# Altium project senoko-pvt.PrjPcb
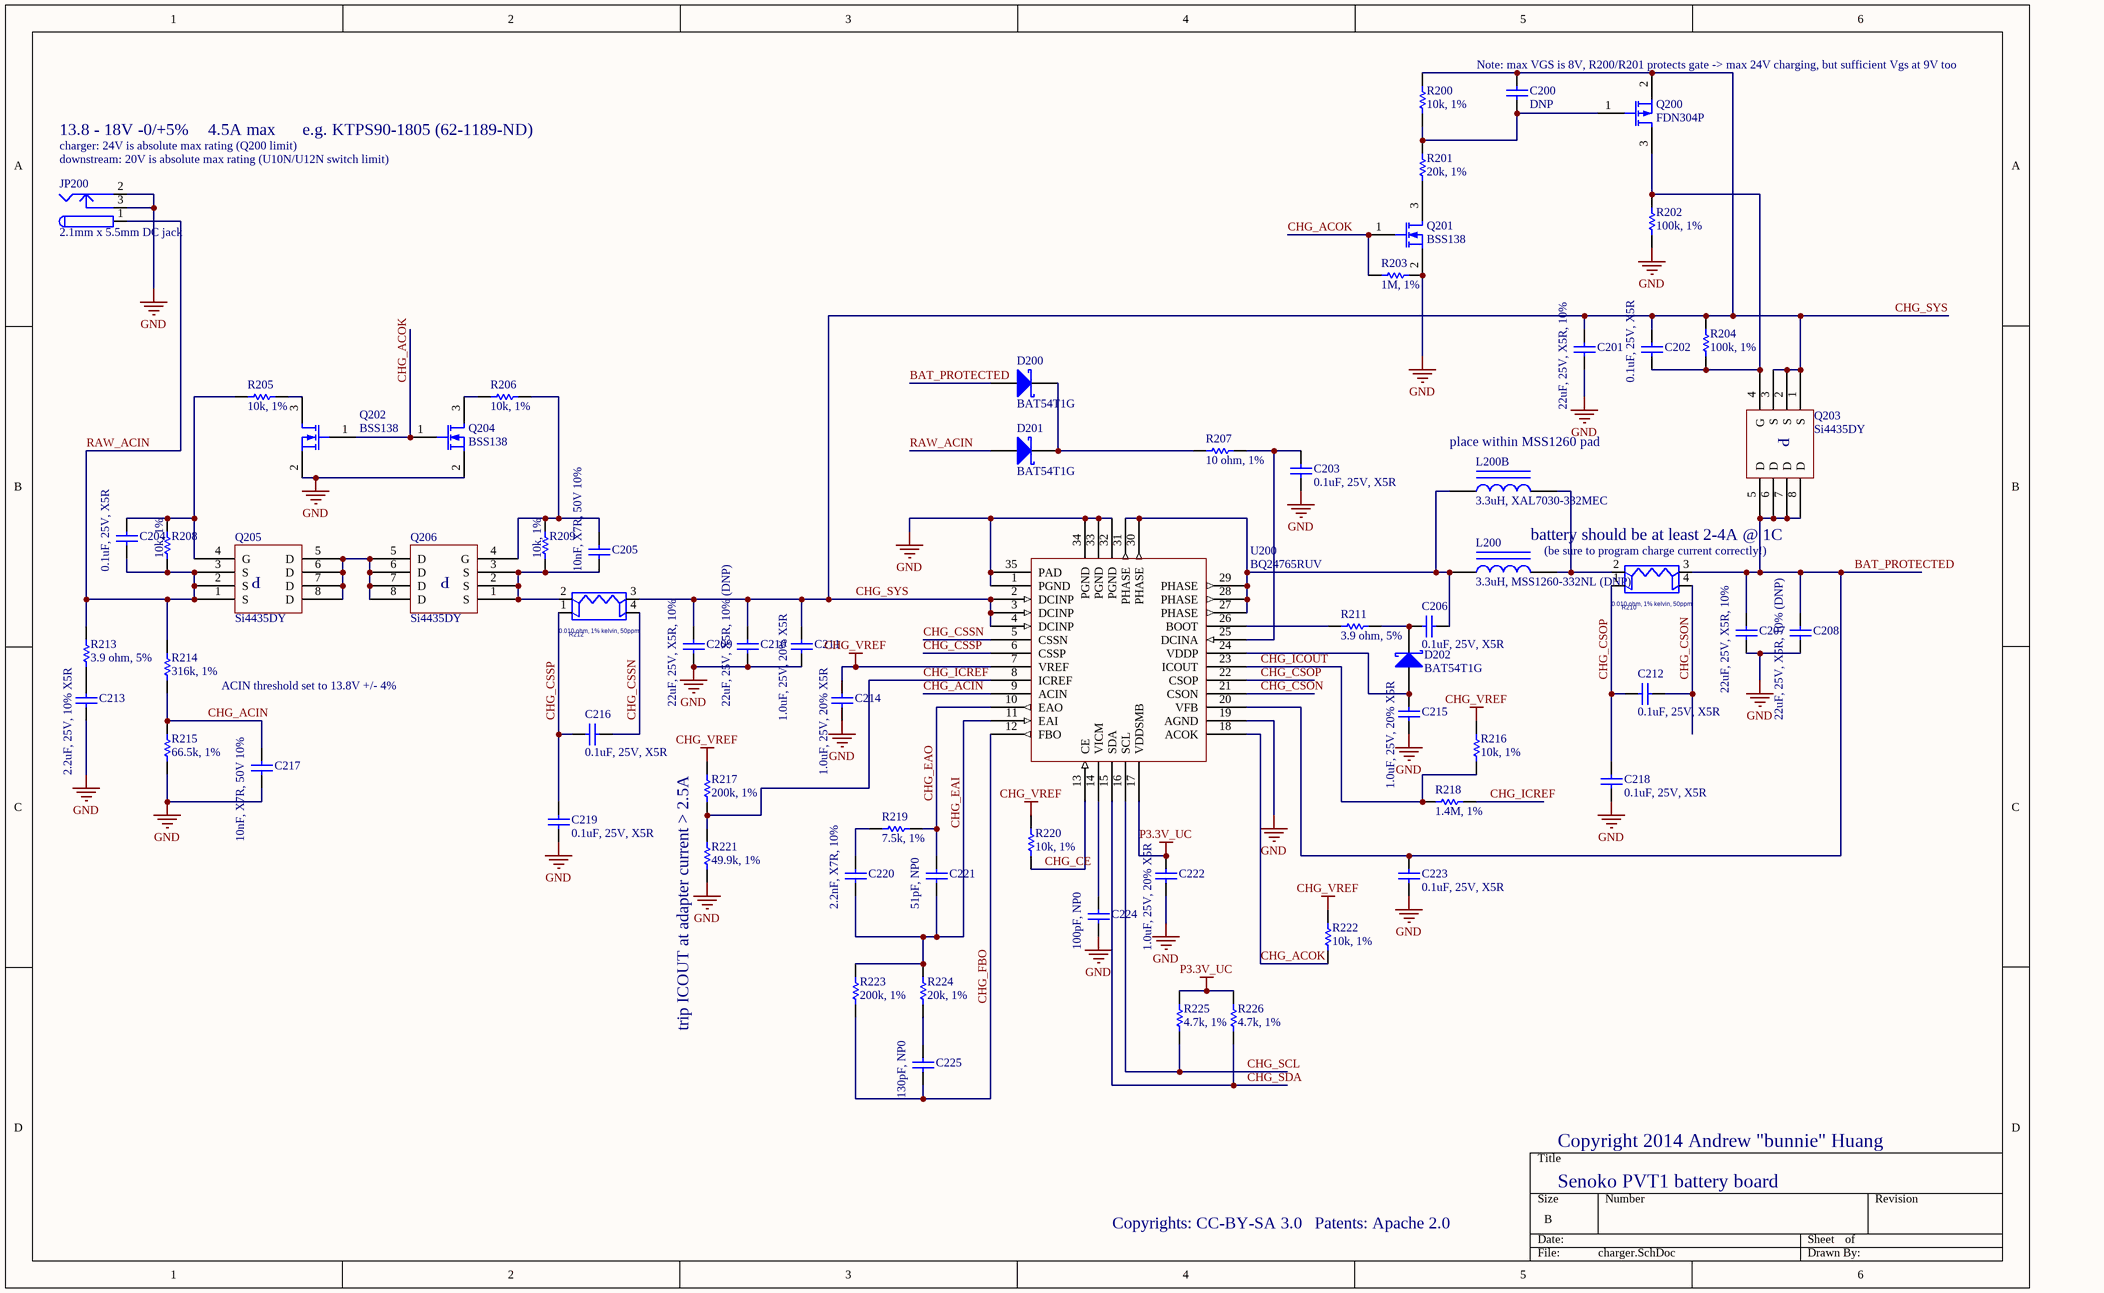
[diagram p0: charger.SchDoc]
3 sheets, 227 parts. Net scope: global (net labels, ports and power ports of the same name join across sheets).
Board file: senoko_pvt1.PcbDoc
Sheets:
  charger.SchDoc
  battery.SchDoc
  controller.SchDoc

## Sheet charger.SchDoc
size B; SheetNumber: 1

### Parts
C200  DNP  [CAPC1005N]
C201  22uF, 25V, X5R, 10%  [CAPC3225N]
C202  0.1uF, 25V, X5R  [CAPC1005N]
C203  0.1uF, 25V, X5R  [CAPC1005N]
C204  0.1uF, 25V, X5R  [CAPC1005N]
C205  10nF, X7R, 50V 10%  [CAPC1005N]
C206  0.1uF, 25V, X5R  [CAPC1005N]
C207  22uF, 25V, X5R, 10%  [CAPC3225N]
C208  22uF, 25V, X5R, 10% (DNP)  [CAPC3225N]
C209  22uF, 25V, X5R, 10%  [CAPC3225N]
C210  22uF, 25V, X5R, 10% (DNP)  [CAPC3225N]
C211  1.0uF, 25V, 20% X5R  [CAPC1608N]
C212  0.1uF, 25V, X5R  [CAPC1005N]
C213  2.2uF, 25V, 10% X5R  [CAPC1608N]
C214  1.0uF, 25V, 20% X5R  [CAPC1608N]
C215  1.0uF, 25V, 20% X5R  [CAPC1608N]
C216  0.1uF, 25V, X5R  [CAPC1005N]
C217  10nF, X7R, 50V 10%  [CAPC1005N]
C218  0.1uF, 25V, X5R  [CAPC1005N]
C219  0.1uF, 25V, X5R  [CAPC1005N]
C220  2.2nF, X7R, 10%  [CAPC1005N]
C221  51pF, NP0  [CAPC1005N]
C222  1.0uF, 25V, 20% X5R  [CAPC1608N]
C223  0.1uF, 25V, X5R  [CAPC1005N]
C224  100pF, NP0  [CAPC1005N]
C225  130pF, NP0  [CAPC1005N]
D200  BAT54T1G  [SOD123]
D201  BAT54T1G  [SOD123]
D202  BAT54T1G  [SOD123]
JP200  2.1mm x 5.5mm DC jack  [CUI_PJ_002AH_SMT]
L200  3.3uH, MSS1260-332NL (DNP)  [COILCRAFT_MSS1048]
L200B  3.3uH, XAL7030-332MEC  [COILCRAFT_XAL7030]
Q200  FDN304P  [SOT23-3N]
Q201  BSS138  [SOT23-3N]
Q202  BSS138  [SOT23-3N]
Q203  Si4435DY  [SOIC127P600-8AN]
Q204  BSS138  [SOT23-3N]
Q205  Si4435DY  [SOIC127P600-8AN]
Q206  Si4435DY  [SOIC127P600-8AN]
R200  10k, 1%  [RESC1005N]
R201  20k, 1%  [RESC1005N]
R202  100k, 1%  [RESC1005N]
R203  1M, 1%  [RESC1005N]
R204  100k, 1%  [RESC1005N]
R205  10k, 1%  [RESC1005N]
R206  10k, 1%  [RESC1005N]
R207  10 ohm, 1%  [RESC1005N]
R208  10k, 1%  [RESC1005N]
R209  10k, 1%  [RESC1005N]
R210  0.010 ohm, 1% kelvin, 50ppm  [OHMITE_LVK_1206_KELVIN]
R211  3.9 ohm, 5%  [RESC1005N]
R212  0.010 ohm, 1% kelvin, 50ppm  [OHMITE_LVK_1206_KELVIN]
R213  3.9 ohm, 5%  [RESC1005N]
R214  316k, 1%  [RESC1005N]
R215  66.5k, 1%  [RESC1005N]
R216  10k, 1%  [RESC1005N]
R217  200k, 1%  [RESC1005N]
R218  1.4M, 1%  [RESC1005N]
R219  7.5k, 1%  [RESC1005N]
R220  10k, 1%  [RESC1005N]
R221  49.9k, 1%  [RESC1005N]
R222  10k, 1%  [RESC1005N]
R223  200k, 1%  [RESC1005N]
R224  20k, 1%  [RESC1005N]
R225  4.7k, 1%  [RESC1005N]
R226  4.7k, 1%  [RESC1005N]
U200  BQ24765RUV  [TI_R-PVQFN-N34]

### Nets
CHG_VREF: C214.1 R216.1 R217.1 R220.1 R222.1 U200.7(VREF)
GND: C201.2 C203.2 C207.2 C208.2 C209.2 C210.2 C211.2 C213.2 C214.2 C215.2 C217.2 C218.1 C219.2 C222.2 C223.1 C224.2 JP200.2 JP200.3 Q201.2(S) Q202.2(S) Q204.2(S) R202.2 R203.1 R215.2 R221.2 U200.1(PGND) U200.19(AGND) U200.32(PGND) U200.33(PGND) U200.34(PGND) U200.35(PAD)
P3.3V_UC: C222.1 R225.1 R226.1 U200.17(VDDSMB)
BAT_PROTECTED: C207.1 C208.1 C223.2 D200.1(A) Q203.5(D) Q203.6(D) Q203.7(D) Q203.8(D) R210.3 U200.20(VFB)
CHG_ACIN: C217.1 R214.2 R215.1 U200.9(ACIN)
CHG_ACOK: Q201.1(G) Q202.1(G) Q204.1(G) R203.2 R222.2 U200.18(ACOK)
CHG_CE: R220.2 U200.13(CE)
CHG_CSON: C212.1 R210.4 U200.21(CSON)
CHG_CSOP: C212.2 C218.2 R210.1 U200.22(CSOP)
CHG_CSSN: C216.2 R212.4 U200.5(CSSN)
CHG_CSSP: C216.1 C219.1 R212.1 U200.6(CSSP)
CHG_EAI: C220.2 C221.2 R223.1 R224.1 U200.11(EAI)
CHG_EAO: C221.1 R219.2 U200.10(EAO)
CHG_FBO: C225.2 R223.2 U200.12(FBO)
CHG_ICOUT: R216.2 R218.2 U200.23(ICOUT)
CHG_ICREF: R217.2 R218.1 R221.1 U200.8(ICREF)
CHG_SCL: R225.2 U200.16(SCL)
CHG_SDA: R226.2 U200.15(SDA)
CHG_SYS: C200.2 C201.1 C202.1 C209.1 C210.1 C211.1 Q200.2(S) Q203.1(S) Q203.2(S) Q203.3(S) R200.1 R204.1 R212.3 U200.2(DCINP) U200.3(DCINP) U200.4(DCINP)
RAW_ACIN: C204.2 D201.1(A) JP200.1 Q205.1(S) Q205.2(S) Q205.3(S) R208.1 R213.1 R214.1
NetC200_1: C200.1 Q200.1(G) R200.2 R201.1
NetC202_2: C202.2 Q200.3(D) Q203.4(G) R202.1 R204.2
NetC203_1: C203.1 R207.2 U200.25(DCINA)
NetC204_1: C204.1 Q205.4(G) R205.1 R208.2
NetC205_1: C205.1 Q206.4(G) R206.2 R209.2
NetC205_2: C205.2 Q206.1(S) Q206.2(S) Q206.3(S) R209.1 R212.2
NetC206_1: C206.1 D202.2(K) R211.2
NetC206_2: C206.2 L200.1 L200B.1 U200.27(PHASE) U200.28(PHASE) U200.29(PHASE) U200.30(PHASE) U200.31(PHASE)
NetC213_1: C213.1 R213.2
NetC215_1: C215.1 D202.1(A) U200.24(VDDP)
NetC220_1: C220.1 R219.1
NetC224_1: C224.1 U200.14(VICM)
NetC225_1: C225.1 R224.2
NetD200_2: D200.2(K) D201.2(K) R207.1
NetL200_2: L200.2 L200B.2 R210.2
NetQ201_3: Q201.3(D) R201.2
NetQ202_3: Q202.3(D) R205.2
NetQ204_3: Q204.3(D) R206.1
NetQ205_5: Q205.5(D) Q205.6(D) Q205.7(D) Q205.8(D) Q206.5(D) Q206.6(D) Q206.7(D) Q206.8(D)
NetR211_1: R211.1 U200.26(BOOT)

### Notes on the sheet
- (near C200) Note: max VGS is 8V, R200/R201 protects gate -> max 24V charging, but sufficient Vgs at 9V too
- 13.8 - 18V -0/+5%
- (near JP200) charger: 24V is absolute max rating (Q200 limit)
- (near JP200) downstream: 20V is absolute max rating (U10N/U12N switch limit)
- 4.5A max
- e.g. KTPS90-1805 (62-1189-ND)
- (near L200B) place within MSS1260 pad
- battery should be at least 2-4A @ 1C
- (be sure to program charge current correctly!)
- ACIN threshold set to 13.8V +/- 4%
- trip ICOUT at adapter current > 2.5A
- Copyright 2014 Andrew "bunnie" Huang
- Copyrights: CC-BY-SA 3.0
- Patents: Apache 2.0
- Senoko PVT1 battery board

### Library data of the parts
C200-C225 = Cap Semi: Capacitor (Semiconductor SIM Model)
D200-D202 = D Schottky: Schottky Diode; Code - JEDEC: DO-214-AA
JP200 = PWR2.5: Low Voltage Power Supply Connector
L200 L200B = Inductor Iron: Magnetic-Core Inductor
Q200 = MOSFET-P: P-Channel MOSFET
Q201 Q202 Q204 = MOSFET-N: N-Channel MOSFET
Q203 Q205 Q206 = Si4435DY: Singre P-channel FET, 8A, 30V
R200 R201 R203 R205-R209 R211 R213-R226 = Res1: Resistor; Value: 100k
R202 R204 = Res1: Resistor
R210 R212 = RES_4TERM: PART_NUMBER: R00034-001; CDS_LMAN_SYM_OUTLINE: -100,25,100,-75; NEEDS_NO_SIZE: TRUE; PATH: I224; PN: #; OriginalSymbolOrigin: (-100,50); LOCATION: RN32; SEC: 1; XY: (-5650,2000); WATTAGE: 1/2W; PHYS_PAGE: 12; PACK_TYPE: RES1206_4T; MFG_PN: LVK12R020FER; MFG: OHMITE; DRAWING: @BROWNSTONE_LIB.BROWNSTONE(SCH_1):PAGE12; CDS_LIB: resistors
U200 = BQ24765RUV: SMBus-controlled battery charger with integrated FETs

## Sheet battery.SchDoc
size B; SheetNumber: 2
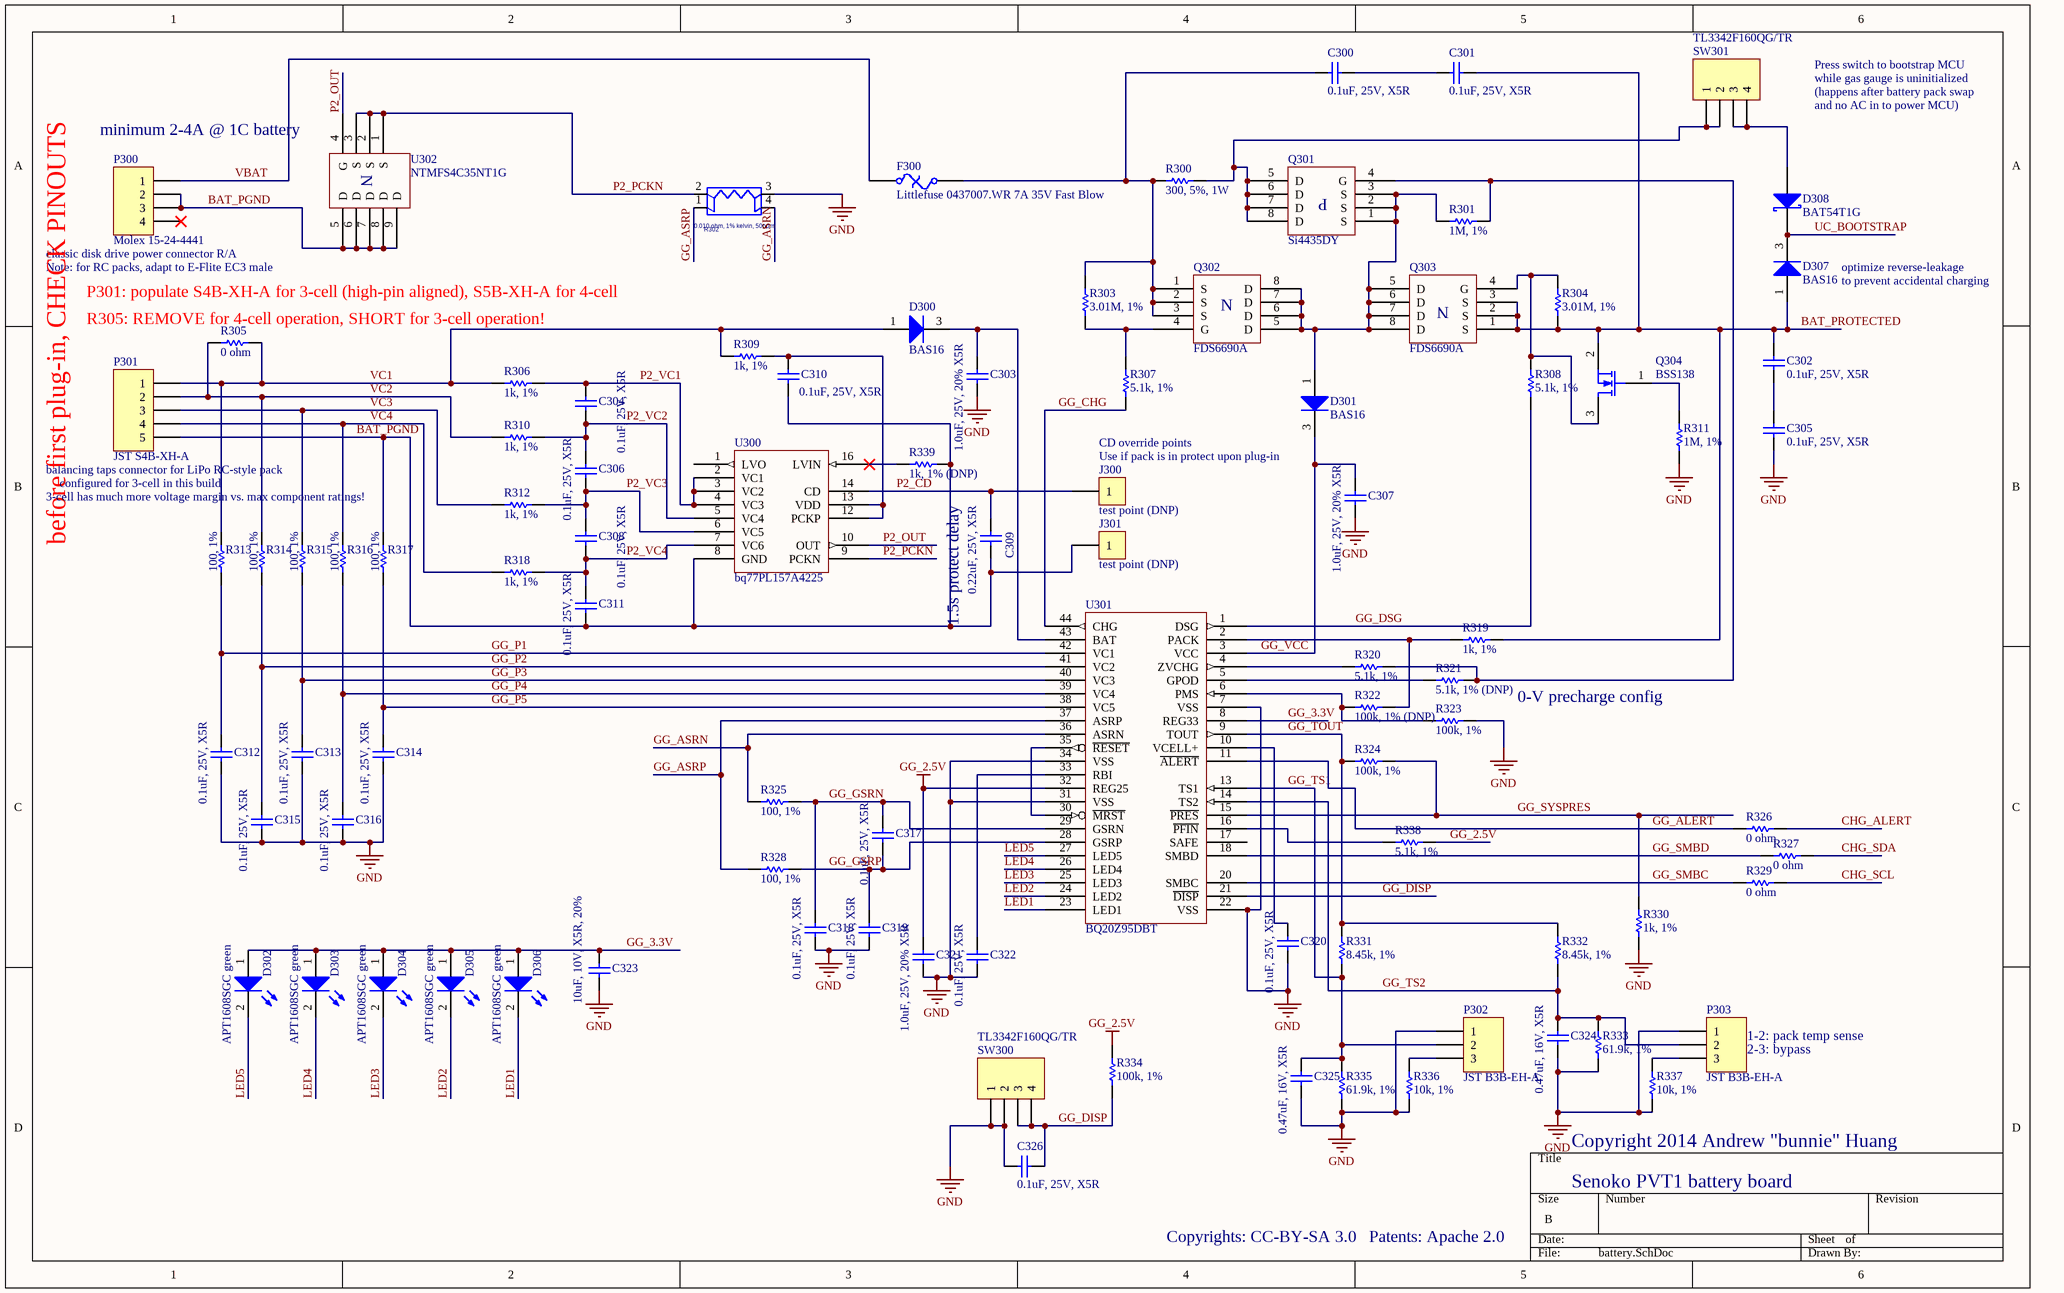
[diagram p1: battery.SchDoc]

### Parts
C300  0.1uF, 25V, X5R  [CAPC1005N]
C301  0.1uF, 25V, X5R  [CAPC1005N]
C302  0.1uF, 25V, X5R  [CAPC1005N]
C303  1.0uF, 25V, 20% X5R  [CAPC1608N]
C304  0.1uF, 25V, X5R  [CAPC1005N]
C305  0.1uF, 25V, X5R  [CAPC1005N]
C306  0.1uF, 25V, X5R  [CAPC1005N]
C307  1.0uF, 25V, 20% X5R  [CAPC1608N]
C308  0.1uF, 25V, X5R  [CAPC1005N]
C309  0.22uF, 25V, X5R  [CAPC1005N]
C310  0.1uF, 25V, X5R  [CAPC1005N]
C311  0.1uF, 25V, X5R  [CAPC1005N]
C312  0.1uF, 25V, X5R  [CAPC1005N]
C313  0.1uF, 25V, X5R  [CAPC1005N]
C314  0.1uF, 25V, X5R  [CAPC1005N]
C315  0.1uF, 25V, X5R  [CAPC1005N]
C316  0.1uF, 25V, X5R  [CAPC1005N]
C317  0.1uF, 25V, X5R  [CAPC1005N]
C318  0.1uF, 25V, X5R  [CAPC1005N]
C319  0.1uF, 25V, X5R  [CAPC1005N]
C320  0.1uF, 25V, X5R  [CAPC1005N]
C321  1.0uF, 25V, 20% X5R  [CAPC1608N]
C322  0.1uF, 25V, X5R  [CAPC1005N]
C323  10uF, 10V, X5R, 20%  [CAPC1608N]
C324  0.47uF, 16V, X5R  [CAPC1005N]
C325  0.47uF, 16V, X5R  [CAPC1005N]
C326  0.1uF, 25V, X5R  [CAPC1005N]
D300  BAS16  [SOT23-3N]
D301  BAS16  [SOT23-3N]
D302  APT1608SGC green  [CD1608-0603]
D303  APT1608SGC green  [CD1608-0603]
D304  APT1608SGC green  [CD1608-0603]
D305  APT1608SGC green  [CD1608-0603]
D306  APT1608SGC green  [CD1608-0603]
D307  BAS16  [SOT23-3N]
D308  BAT54T1G  [SOD123]
F300  Littlefuse 0437007.WR 7A 35V Fast Blow  [RESC3216N]
J300  test point (DNP)  [TP_HOLE]
J301  test point (DNP)  [TP_HOLE]
P300  Molex 15-24-4441  [MOLEX_15-24-4441]
P301  JST S4B-XH-A  [JST_S5B-XH-A_OPT4]
P302  JST B3B-EH-A  [JST_B3B_EH_A]
P303  JST B3B-EH-A  [JST_B3B_EH_A]
Q301  Si4435DY  [SOIC127P600-8AN]
Q302  FDS6690A  [SOIC127P600-8AN]
Q303  FDS6690A  [SOIC127P600-8AN]
Q304  BSS138  [SOT23-3N]
R300  300, 5%, 1W  [RESC6432N]
R301  1M, 1%  [RESC1005N]
R302  0.010 ohm, 1% kelvin, 50ppm  [OHMITE_LVK_1206_KELVIN]
R303  3.01M, 1%  [RESC1005N]
R304  3.01M, 1%  [RESC1005N]
R305  0 ohm  [RESC1005N]
R306  1k, 1%  [RESC1005N]
R307  5.1k, 1%  [RESC1005N]
R308  5.1k, 1%  [RESC1005N]
R309  1k, 1%  [RESC1005N]
R310  1k, 1%  [RESC1005N]
R311  1M, 1%  [RESC1005N]
R312  1k, 1%  [RESC1005N]
R313  100, 1%  [RESC1005N]
R314  100, 1%  [RESC1005N]
R315  100, 1%  [RESC1005N]
R316  100, 1%  [RESC1005N]
R317  100, 1%  [RESC1005N]
R318  1k, 1%  [RESC1005N]
R319  1k, 1%  [RESC1005N]
R320  5.1k, 1%  [RESC1005N]
R321  5.1k, 1% (DNP)  [RESC1005N]
R322  100k, 1% (DNP)  [RESC1005N]
R323  100k, 1%  [RESC1005N]
R324  100k, 1%  [RESC1005N]
R325  100, 1%  [RESC1005N]
R326  0 ohm  [RESC1005N]
R327  0 ohm  [RESC1005N]
R328  100, 1%  [RESC1005N]
R329  0 ohm  [RESC1005N]
R330  1k, 1%  [RESC1005N]
R331  8.45k, 1%  [RESC1005N]
R332  8.45k, 1%  [RESC1005N]
R333  61.9k, 1%  [RESC1005N]
R334  100k, 1%  [RESC1005N]
R335  61.9k, 1%  [RESC1005N]
R336  10k, 1%  [RESC1005N]
R337  10k, 1%  [RESC1005N]
R338  5.1k, 1%  [RESC1005N]
R339  1k, 1% (DNP)  [RESC1005N]
SW300  TL3342F160QG/TR  [SWITCH_TS-1187A]
SW301  TL3342F160QG/TR  [SWITCH_TS-1187A]
U300  bq77PL157A4225  [TSOP65P640-16AN]
U301  BQ20Z95DBT  [TSSOP50P640-44N]
U302  NTMFS4C35NT1G  [ONSEMI_DFN5_5x6_1.27P]

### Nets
GG_2.5V: C321.1 R334.2 R338.1 U301.32(REG25)
GND: C303.2 C305.1 C307.2 C312.2 C313.2 C314.2 C315.2 C316.2 C318.2 C319.2 C320.2 C321.2 C322.2 C323.2 C324.2 C325.2 C326.2 P302.1 P303.1 R302.3 R311.2 R323.2 R330.2 R333.1 R335.1 R336.1 R337.1 SW300.1 SW300.2 U301.7(VSS) U301.22(VSS) U301.31(VSS) U301.34(VSS)
BAT_PGND: C309.2 C310.2 C311.2 J301.1 P300.2 P300.3 P301.5 R317.1 R339.2 U300.8(GND) U302.5(D) U302.6(D) U302.7(D) U302.8(D) U302.9(D)
BAT_PROTECTED: C301.1 C302.2 D307.1(A) Q303.1(S) Q303.2(S) Q303.3(S) Q304.2(S) R304.2 R319.1
CHG_ALERT: R326.2
CHG_SCL: R329.2
CHG_SDA: R327.2
GG_3.3V: C323.1 D302.1(A) D303.1(A) D304.1(A) D305.1(A) D306.1(A) U301.8(REG33)
GG_ALERT: R326.1 U301.11(~{ALERT})
GG_ASRN: R302.4 R325.2 U301.36(ASRN)
GG_ASRP: R302.1 R328.2 U301.37(ASRP)
GG_CHG: R307.2 U301.44(CHG)
GG_DISP: C326.1 R334.1 SW300.3 SW300.4 U301.21(~{DISP})
GG_DSG: R308.2 U301.1(DSG)
GG_GSRN: C317.1 C318.1 R325.1 U301.29(GSRN)
GG_GSRP: C317.2 C319.1 R328.1 U301.28(GSRP)
GG_P1: C312.1 R313.2 U301.42(VC1)
GG_P2: C315.1 R314.2 U301.41(VC2)
GG_P3: C313.1 R315.2 U301.40(VC3)
GG_P4: C316.1 R316.2 U301.39(VC4)
GG_P5: C314.1 R317.2 U301.38(VC5)
GG_SMBC: R329.1 U301.20(SMBC)
GG_SMBD: R327.1 U301.18(SMBD)
GG_SYSPRES: R324.2 R330.1 U301.15(~{PRES})
GG_TOUT: R324.1 R331.2 R332.2 U301.9(TOUT)
GG_TS1: C325.1 P302.2 R331.1 R335.2 U301.13(TS1)
GG_TS2: C324.1 P303.2 R332.1 R333.2 U301.14(TS2)
GG_VCC: C307.1 D301.3(K) U301.3(VCC)
LED1: D306.2(K) U301.23(LED1)
LED2: D305.2(K) U301.24(LED2)
LED3: D304.2(K) U301.25(LED3)
LED4: D303.2(K) U301.26(LED4)
LED5: D302.2(K) U301.27(LED5)
P2_CD: C309.1 J300.1 U300.14(CD)
P2_OUT: U300.10(OUT) U302.4(G)
P2_PCKN: R302.2 U300.9(PCKN) U302.1(S) U302.2(S) U302.3(S)
P2_VC1: C304.1 R306.2 U300.2(VC1) U300.3(VC2) U300.4(VC3)
P2_VC2: C304.2 C306.1 R310.2 U300.5(VC4)
P2_VC3: C306.2 C308.1 R312.2 U300.6(VC5)
P2_VC4: C308.2 C311.1 R318.2 U300.7(VC6)
UC_BOOTSTRAP: D307.3(K) D308.2(K)
VBAT: F300.1 P300.1
VC1: D300.1(A) P301.1 R305.2 R306.1 R309.1 R313.1
VC2: P301.2 R305.1 R310.1 R314.1
VC3: P301.3 R312.1 R315.1
VC4: P301.4 R316.1 R318.1
NetC300_1: C300.1 C301.2
NetC300_2: C300.2 F300.2 Q302.1(S) Q302.2(S) Q302.3(S) R300.2 R303.1
NetC302_1: C302.1 C305.2
NetC303_1: C303.1 D300.3(K) U301.43(BAT)
NetC310_1: C310.1 R309.2 U300.12(PCKP) U300.13(VDD)
NetC320_1: C320.1 U301.10(VCELL+)
NetC322_1: C322.1 U301.33(RBI)
NetD301_1: D301.1(A) Q301.1(S) Q301.2(S) Q301.3(S) Q302.5(D) Q302.6(D) Q302.7(D) Q302.8(D) Q303.5(D) Q303.6(D) Q303.7(D) Q303.8(D) R301.2
NetD308_1: D308.1(A) SW301.3 SW301.4
NetP302_3: P302.3 R336.2
NetP303_3: P303.3 R337.2
NetQ301_4: Q301.4(G) R301.1 R320.1 R321.1
NetQ301_5: Q301.5(D) Q301.6(D) Q301.7(D) Q301.8(D) R300.1 SW301.1 SW301.2
NetQ302_4: Q302.4(G) R303.2 R307.1
NetQ303_4: Q303.4(G) Q304.3(D) R304.1 R308.1
NetQ304_1: Q304.1(G) R311.1
NetR319_2: R319.2 R322.2 U301.2(PACK)
NetR320_2: R320.2 U301.4(ZVCHG)
NetR321_2: R321.2 U301.5(GPOD)
NetR322_1: R322.1 R323.1 U301.6(PMS)
NetR338_2: R338.2 U301.16(~{PFIN})
NetR339_1: R339.1 U300.16(LVIN)
NetU301_30: U301.30(~{MRST}) U301.35(~{RESET})

Not connected (* = marked no-connect by the designer): P300 4*; U300 1(LVO); U301 17(SAFE)

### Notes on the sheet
- Press switch to bootstrap MCU
- while gas gauge is uninitialized
- (happens after battery pack swap
- minimum 2-4A @ 1C battery
- and no AC in to power MCU)
- (near P300) classic disk drive power connector R/A
- Note: for RC packs, adapt to E-Flite EC3 male
- P301: populate S4B-XH-A for 3-cell (high-pin aligned), S5B-XH-A for 4-cell
- optimize reverse-leakage
- to prevent accidental charging
- (near R305) R305: REMOVE for 4-cell operation, SHORT for 3-cell operation!
- (near P301) balancing taps connector for LiPo RC-style pack
- 3-cell has much more voltage margin vs. max component ratings!
- configured for 3-cell in this build
- Use if pack is in protect upon plug-in
- CD override points
- before first plug-in, CHECK PINOUTS
- (near R339) 1.5s protect delay
- 0-V precharge config
- (near P303) 1-2: pack temp sense
- (near P303) 2-3: bypass
- (near R337) Copyright 2014 Andrew "bunnie" Huang
- Copyrights: CC-BY-SA 3.0
- Patents: Apache 2.0
- Senoko PVT1 battery board

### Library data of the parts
C300-C326 = Cap Semi: Capacitor (Semiconductor SIM Model)
D300 D301 D307 = Diode 1N4148: Silicon diode
D302-D306 = LED2: Typical RED, GREEN, YELLOW, AMBER GaAs LED
D308 = D Schottky: Schottky Diode; Code - JEDEC: DO-214-AA
F300 = Fuse Thermal: Thermal Fuse
J300 J301 = CON1: Connector
P300 = Header 4: Classic PC hard drive power connector, RA
P301 = Header 5: JST S4B-XH-A 2.5mm RA connector, stuffed in 5-pin slot, high pin aligned
P302 P303 = Header 3: Header, 3-Pin
Q301 = Si4435DY: Singre P-channel FET, 8A, 30V
Q302 Q303 = FDS6690A: Single N-channel FET, 11A, 30V
Q304 = MOSFET-N: N-Channel MOSFET
R300 R301 R303-R321 R325-R333 R335-R339 = Res1: Resistor; Value: 100k
R302 = RES_4TERM: as R210 on sheet charger
R322-R324 R334 = Res1: Resistor
SW300 SW301 = Header 4: Chi Fung TS-1187A
U300 = bq77PL157A: Voltage protection for 3-series to 6-series Li batteries
U301 = BQ20Z95DBT: SBS 1.1-Compliant Gas Gauge and Protection with Impedance Track (TM)
U302 = NTMFS4841N: N channel power MOSFET, 30V, 57A SO-8FL

## Sheet controller.SchDoc
size B; SheetNumber: 3
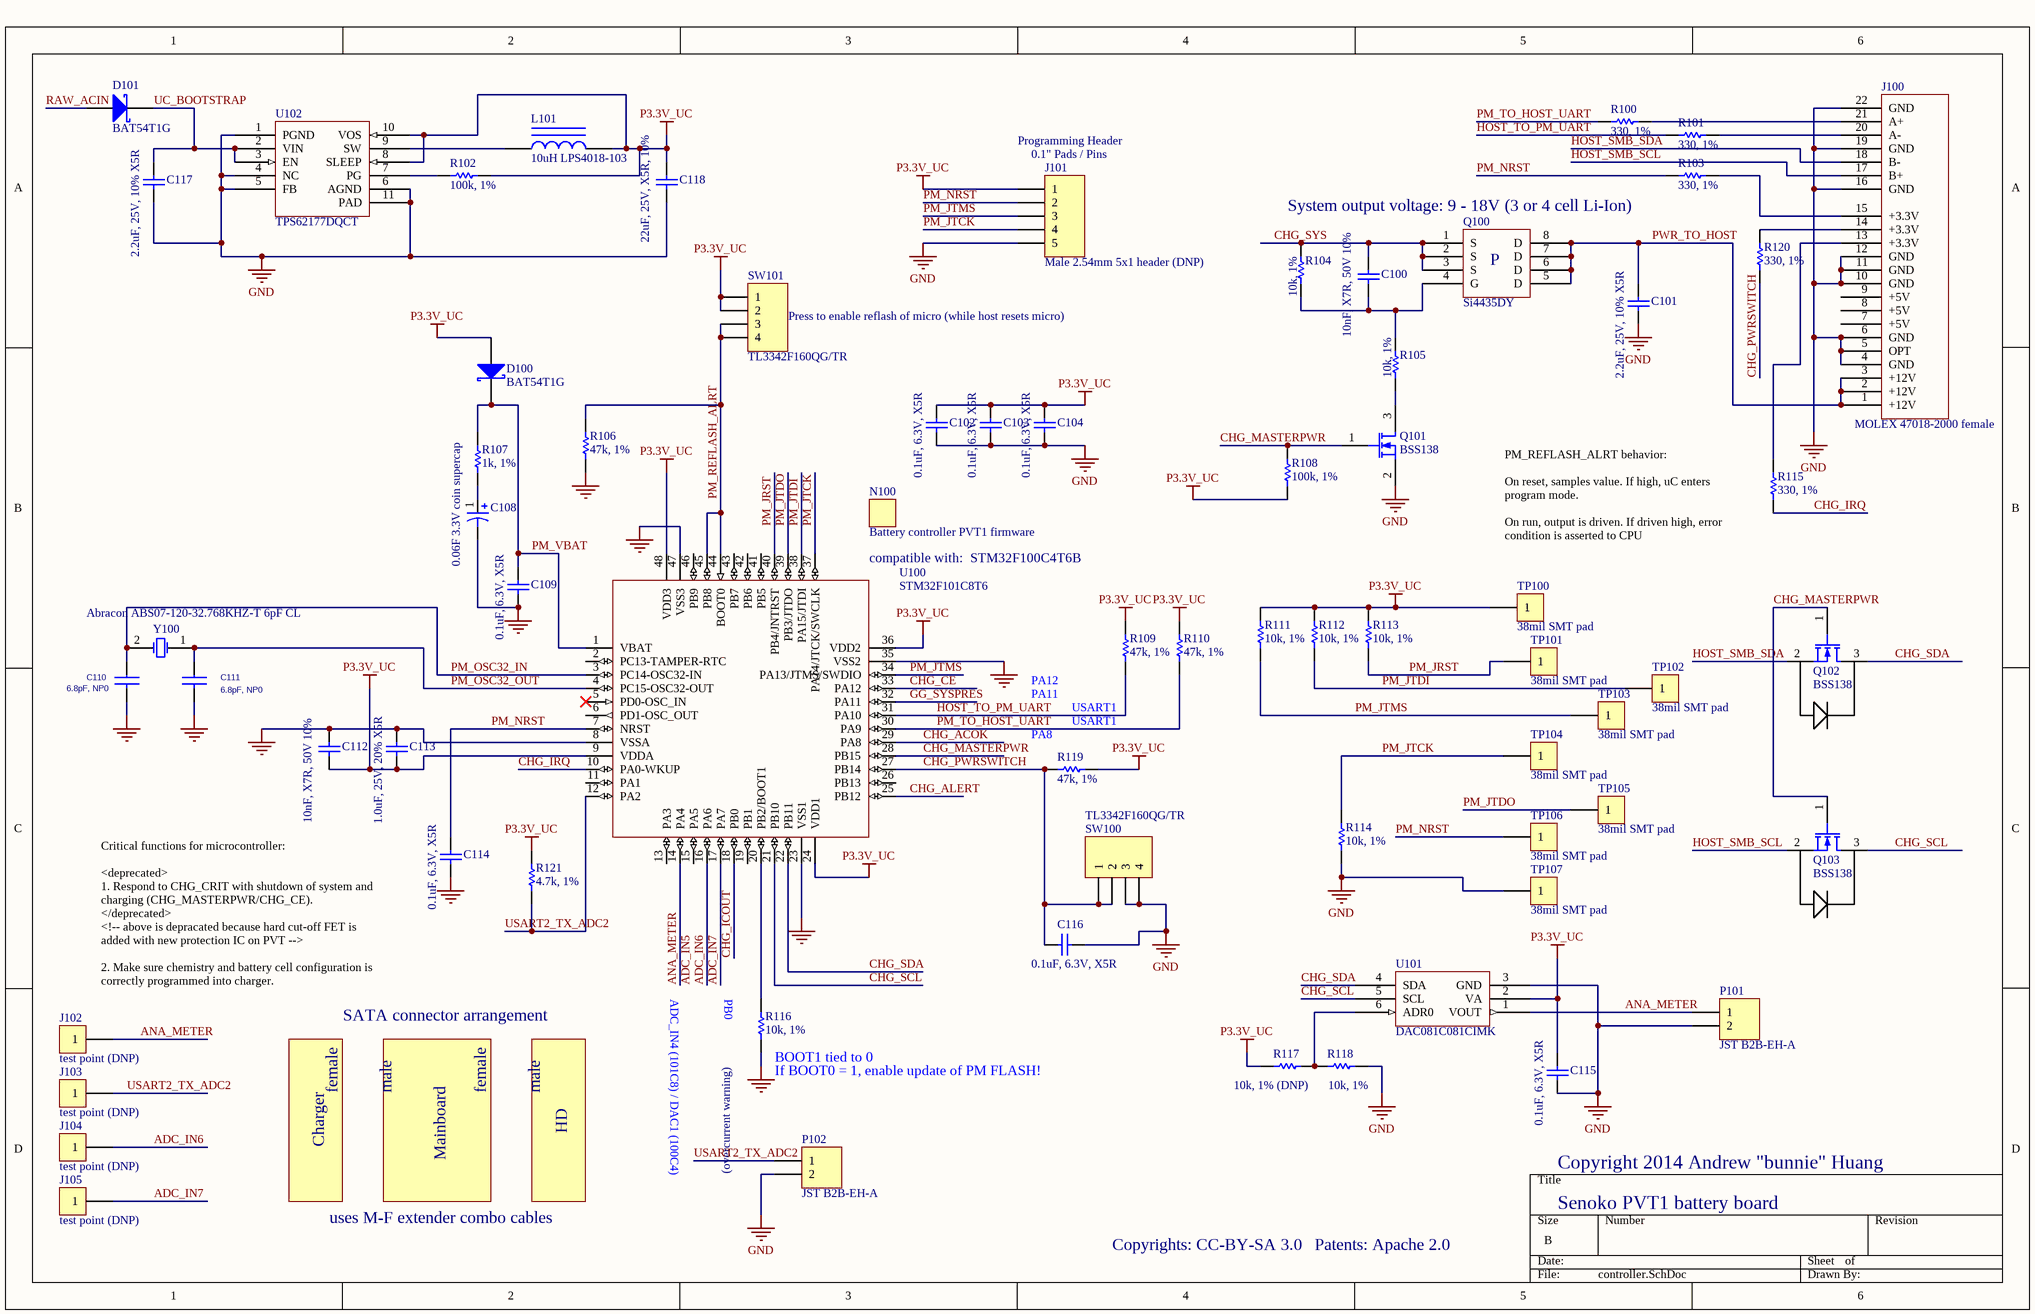
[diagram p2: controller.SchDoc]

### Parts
C100  10nF, X7R, 50V 10%  [CAPC1005N]
C101  2.2uF, 25V, 10% X5R  [CAPC1608N]
C102  0.1uF, 6.3V, X5R  [CAPC0603N_B]
C103  0.1uF, 6.3V, X5R  [CAPC0603N_B]
C104  0.1uF, 6.3V, X5R  [CAPC0603N_B]
C108  0.06F 3.3V coin supercap  [TAIYO_YUDEN_PAS414HR-VA5R]
C109  0.1uF, 6.3V, X5R  [CAPC0603N_B]
C110  6.8pF, NP0  [CAPC1005N]
C111  6.8pF, NP0  [CAPC1005N]
C112  10nF, X7R, 50V 10%  [CAPC1005N]
C113  1.0uF, 25V, 20% X5R  [CAPC1608N]
C114  0.1uF, 6.3V, X5R  [CAPC0603N_B]
C115  0.1uF, 6.3V, X5R  [CAPC0603N_B]
C116  0.1uF, 6.3V, X5R  [CAPC0603N_B]
C117  2.2uF, 25V, 10% X5R  [CAPC1608N]
C118  22uF, 25V, X5R, 10%  [CAPC3225N]
D100  BAT54T1G  [SOD123]
D101  BAT54T1G  [SOD123]
J100  MOLEX 47018-2000 female  [SATA_MOLEX_47018_2000]
J101  Male 2.54mm 5x1 header (DNP)  [HDR1X5]
J102  test point (DNP)  [TP_SMT_38mil]
J103  test point (DNP)  [TP_SMT_38mil]
J104  test point (DNP)  [TP_SMT_38mil]
J105  test point (DNP)  [TP_SMT_38mil]
L101  10uH LPS4018-103  [COILCRAFT_LPS4018]
N100  Battery controller PVT1 firmware
P101  JST B2B-EH-A  [JST_B2B_EH_A]
P102  JST B2B-EH-A  [JST_B2B_EH_A]
Q100  Si4435DY  [SOIC127P600-8AN]
Q101  BSS138  [SOT23-3N]
Q102  BSS138  [SOT23-3N]
Q103  BSS138  [SOT23-3N]
R100  330, 1%  [RESC1005N]
R101  330, 1%  [RESC1005N]
R102  100k, 1%  [RESC1005N]
R103  330, 1%  [RESC1005N]
R104  10k, 1%  [RESC1005N]
R105  10k, 1%  [RESC1005N]
R106  47k, 1%  [RESC1005N]
R107  1k, 1%  [RESC1005N]
R108  100k, 1%  [RESC1005N]
R109  47k, 1%  [RESC1005N]
R110  47k, 1%  [RESC1005N]
R111  10k, 1%  [RESC1005N]
R112  10k, 1%  [RESC1005N]
R113  10k, 1%  [RESC1005N]
R114  10k, 1%  [RESC1005N]
R115  330, 1%  [RESC1005N]
R116  10k, 1%  [RESC1005N]
R117  10k, 1% (DNP)  [RESC1005N]
R118  10k, 1%  [RESC1005N]
R119  47k, 1%  [RESC1005N]
R120  330, 1%  [RESC1005N]
R121  4.7k, 1%  [RESC1005N]
SW100  TL3342F160QG/TR  [SWITCH_TS-1187A]
SW101  TL3342F160QG/TR  [SWITCH_TS-1187A]
TP100  38mil SMT pad  [TP_SMT_38mil]
TP101  38mil SMT pad  [TP_SMT_38mil]
TP102  38mil SMT pad  [TP_SMT_38mil]
TP103  38mil SMT pad  [TP_SMT_38mil]
TP104  38mil SMT pad  [TP_SMT_38mil]
TP105  38mil SMT pad  [TP_SMT_38mil]
TP106  38mil SMT pad  [TP_SMT_38mil]
TP107  38mil SMT pad  [TP_SMT_38mil]
U100  STM32F101C8T6  [TSQFP50P900X900-48N]
U101  DAC081C081CIMK  [SOT26A-6N]
U102  TPS62177DQCT  [TI_DQC_R_PWSON_N10]
Y100  Abracon ABS07-120-32.768KHZ-T 6pF CL  [ABS07-120]

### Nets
GND: C101.2 C102.2 C103.2 C104.2 C108.2 C109.2 C110.2 C111.2 C112.1 C113.1 C114.2 C115.2 C116.1 C117.2 C118.2 J100.4(GND) J100.5(OPT) J100.6(GND) J100.10(GND) J100.11(GND) J100.12(GND) J100.16(GND) J100.19(GND) J100.22(GND) J101.5 P101.2 P102.2 Q101.2(S) R106.1 R114.1 R116.1 R118.2 SW100.3 SW100.4 TP107.1 U100.8(VSSA) U100.23(VSS1) U100.35(VSS2) U100.47(VSS3) U101.3(GND) U102.1(PGND) U102.4(NC) U102.5(FB) U102.6(AGND) U102.11(PAD)
P3.3V_UC: C102.1 C103.1 C104.1 C112.2 C113.2 C115.1 C118.1 D100.1(A) J101.1 L101.2 R102.1 R108.1 R109.2 R110.2 R111.2 R112.2 R113.2 R117.1 R119.2 R121.2 SW101.1 SW101.2 TP100.1 U100.9(VDDA) U100.24(VDD1) U100.36(VDD2) U100.48(VDD3) U101.2(VA) U102.8(SLEEP) U102.10(VOS)
ADC_IN6: J104.1 U100.16(PA6)
ADC_IN7: J105.1 U100.17(PA7)
ANA_METER: J102.1 P101.1 U100.14(PA4) U101.1(VOUT)
CHG_ACOK: U100.29(PA8)
CHG_ALERT: U100.25(PB12)
CHG_CE: U100.33(PA12)
CHG_ICOUT: U100.18(PB0)
CHG_IRQ: R115.1 U100.10(PA0-WKUP)
CHG_MASTERPWR: Q101.1(G) Q102.1(G) Q103.1(G) R108.2 U100.28(PB15)
CHG_PWRSWITCH: C116.2 R119.1 R120.1 SW100.1 SW100.2 U100.27(PB14)
CHG_SCL: Q103.3(D) U100.21(PB10) U101.5(SCL)
CHG_SDA: Q102.3(D) U100.22(PB11) U101.4(SDA)
CHG_SYS: C100.1 Q100.1(S) Q100.2(S) Q100.3(S) R104.2
GG_SYSPRES: U100.32(PA11)
HOST_SMB_SCL: J100.17(B+) Q103.2(S)
HOST_SMB_SDA: J100.18(B-) Q102.2(S)
HOST_TO_PM_UART: R101.1 R109.1 U100.31(PA10)
PM_JRST: R113.1 TP101.1 U100.40(PB4/JNTRST)
PM_JTCK: J101.4 R114.2 TP104.1 U100.37(PA14/JTCK/SWCLK)
PM_JTDI: R112.1 TP102.1 U100.38(PA15/JTDI)
PM_JTDO: TP105.1 U100.39(PB3/JTDO)
PM_JTMS: J101.3 R111.1 TP103.1 U100.34(PA13/JTMS/SWDIO)
PM_NRST: C114.1 J101.2 R103.1 TP106.1 U100.7(NRST)
PM_OSC32_IN: C110.1 U100.3(PC14-OSC32-IN) Y100.2(OSC2)
PM_OSC32_OUT: C111.1 U100.4(PC15-OSC32-OUT) Y100.1(OSC1)
PM_REFLASH_ALRT: R106.2 SW101.3 SW101.4 U100.44(BOOT0) U100.45(PB8)
PM_TO_HOST_UART: R100.1 R110.1 U100.30(PA9)
PM_VBAT: C109.1 D100.2(K) R107.2 U100.1(VBAT)
PWR_TO_HOST: C101.1 J100.1(+12V) J100.2(+12V) J100.3(+12V) Q100.5(D) Q100.6(D) Q100.7(D) Q100.8(D)
RAW_ACIN: D101.1(A)
UC_BOOTSTRAP: C117.1 D101.2(K) U102.2(VIN) U102.3(EN)
USART2_TX_ADC2: J103.1 P102.1 R121.1 U100.12(PA2)
NetC100_2: C100.2 Q100.4(G) R104.1 R105.2
NetC108_1: C108.1 R107.1
NetJ100_13: J100.13(+3.3V) R115.2
NetJ100_14: J100.14(+3.3V) R120.2
NetJ100_15: J100.15(+3.3V) R103.2
NetJ100_20: J100.20(A-) R101.2
NetJ100_21: J100.21(A+) R100.2
NetL101_1: L101.1 U102.9(SW)
NetQ101_3: Q101.3(D) R105.1
NetR102_2: R102.2 U102.7(PG)
NetR116_2: R116.2 U100.20(PB2/BOOT1)
NetR117_2: R117.2 R118.1 U101.6(ADR0)

Not connected (* = marked no-connect by the designer): J100 7(+5V) 8(+5V) 9(+5V); U100 2(PC13-TAMPER-RTC) 5(PD0-OSC_IN)* 6(PD1-OSC_OUT) 11(PA1) 13(PA3) 15(PA5) 19(PB1) 26(PB13) 41(PB5) 42(PB6) 43(PB7) 46(PB9)

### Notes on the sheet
- (near J101) Programming Header
- (near J101) 0.1" Pads / Pins
- System output voltage: 9 - 18V (3 or 4 cell Li-Ion)
- (near SW101) Press to enable reflash of micro (while host resets micro)
- (near U100) compatible with:  STM32F100C4T6B
- (near TP100) PM_REFLASH_ALRT behavior:
  On reset, samples value. If high, uC enters program mode.
  On run, output is driven. If driven high, error condition is asserted to CPU
- PA11
- PA12
- USART1
- (near R119) PA8
- Critical functions for microcontroller:
  <deprecated>
  1. Respond to CHG_CRIT with shutdown of system and charging (CHG_MASTERPWR/CHG_CE).
  </deprecated>
  <!-- above is depracated because hard cut-off FET is added with new protection IC on PVT -->
  2. Make sure chemistry and battery cell configuration is correctly programmed into charger.
- ADC_IN4 (101C8) / DAC1 (100C4)
- (near R116) PB0
- SATA connector arrangement
- (near R116) BOOT1 tied to 0
- female
- male
- HD
- (near R116) If BOOT0 = 1, enable update of PM FLASH!
- Charger
- Mainboard
- (near R116) (overcurrent warning)
- Copyright 2014 Andrew "bunnie" Huang
- uses M-F extender combo cables
- Copyrights: CC-BY-SA 3.0
- Patents: Apache 2.0
- Senoko PVT1 battery board
- Labels drawn without touching a wire or pin: ADC_IN5

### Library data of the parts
C100-C104 C109 C112-C118 = Cap Semi: Capacitor (Semiconductor SIM Model)
C108 = Cap Pol3: Taiyo Yuden PAS414HR-VA5R
C110 C111 = CAP NP: Right: 20; Bottom: 10
D100 D101 = D Schottky: Schottky Diode; Code - JEDEC: DO-214-AA
J100 = SATA_22P_HEADER: SATA+Power connector
J101 = Header 5: Header, 5-Pin
J102-J105 TP100-TP107 = CON1: Connector
L101 = Inductor Iron: Magnetic-Core Inductor
N100 = NOTE: Placeholder for non-electrical BOM items
P101 P102 = Header 2: Header, 2-Pin
Q100 = Si4435DY: Singre P-channel FET, 8A, 30V
Q101-Q103 = MOSFET-N: N-Channel MOSFET
R100 R101 R103-R107 R109-R121 = Res1: Resistor; Value: 100k
R102 R108 = Res1: Resistor
SW100 SW101 = Header 4: Chi Fung TS-1187A
U100 = STM32F103C8T6: 32-bit ARM Coretex high performance microcontroller
U101 = DAC081C81CIMK: Single 8-bit DAC for I2C bus
U102 = TPS62177DQCT: 28V, 0.5A step-down converter with sleep mode
Y100 = XTAL: Crystal Oscillator

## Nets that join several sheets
GND: charger (31 pins), battery (33 pins), controller (45 pins)
P3.3V_UC: charger (C222.1 R225.1 R226.1 U200.17), controller (30 pins)
BAT_PROTECTED: charger (10 pins), battery (9 pins)
CHG_ACOK: charger (6 pins), controller (U100.29)
CHG_ALERT: battery (R326.2), controller (U100.25)
CHG_CE: charger (R220.2 U200.13), controller (U100.33)
CHG_ICOUT: charger (R216.2 R218.2 U200.23), controller (U100.18)
CHG_SCL: charger (R225.2 U200.16), battery (R329.2), controller (Q103.3 U100.21 U101.5)
CHG_SDA: charger (R226.2 U200.15), battery (R327.2), controller (Q102.3 U100.22 U101.4)
CHG_SYS: charger (16 pins), controller (5 pins)
GG_SYSPRES: battery (R324.2 R330.1 U301.15), controller (U100.32)
RAW_ACIN: charger (9 pins), controller (D101.1)
UC_BOOTSTRAP: battery (D307.3 D308.2), controller (C117.1 D101.2 U102.2 U102.3)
